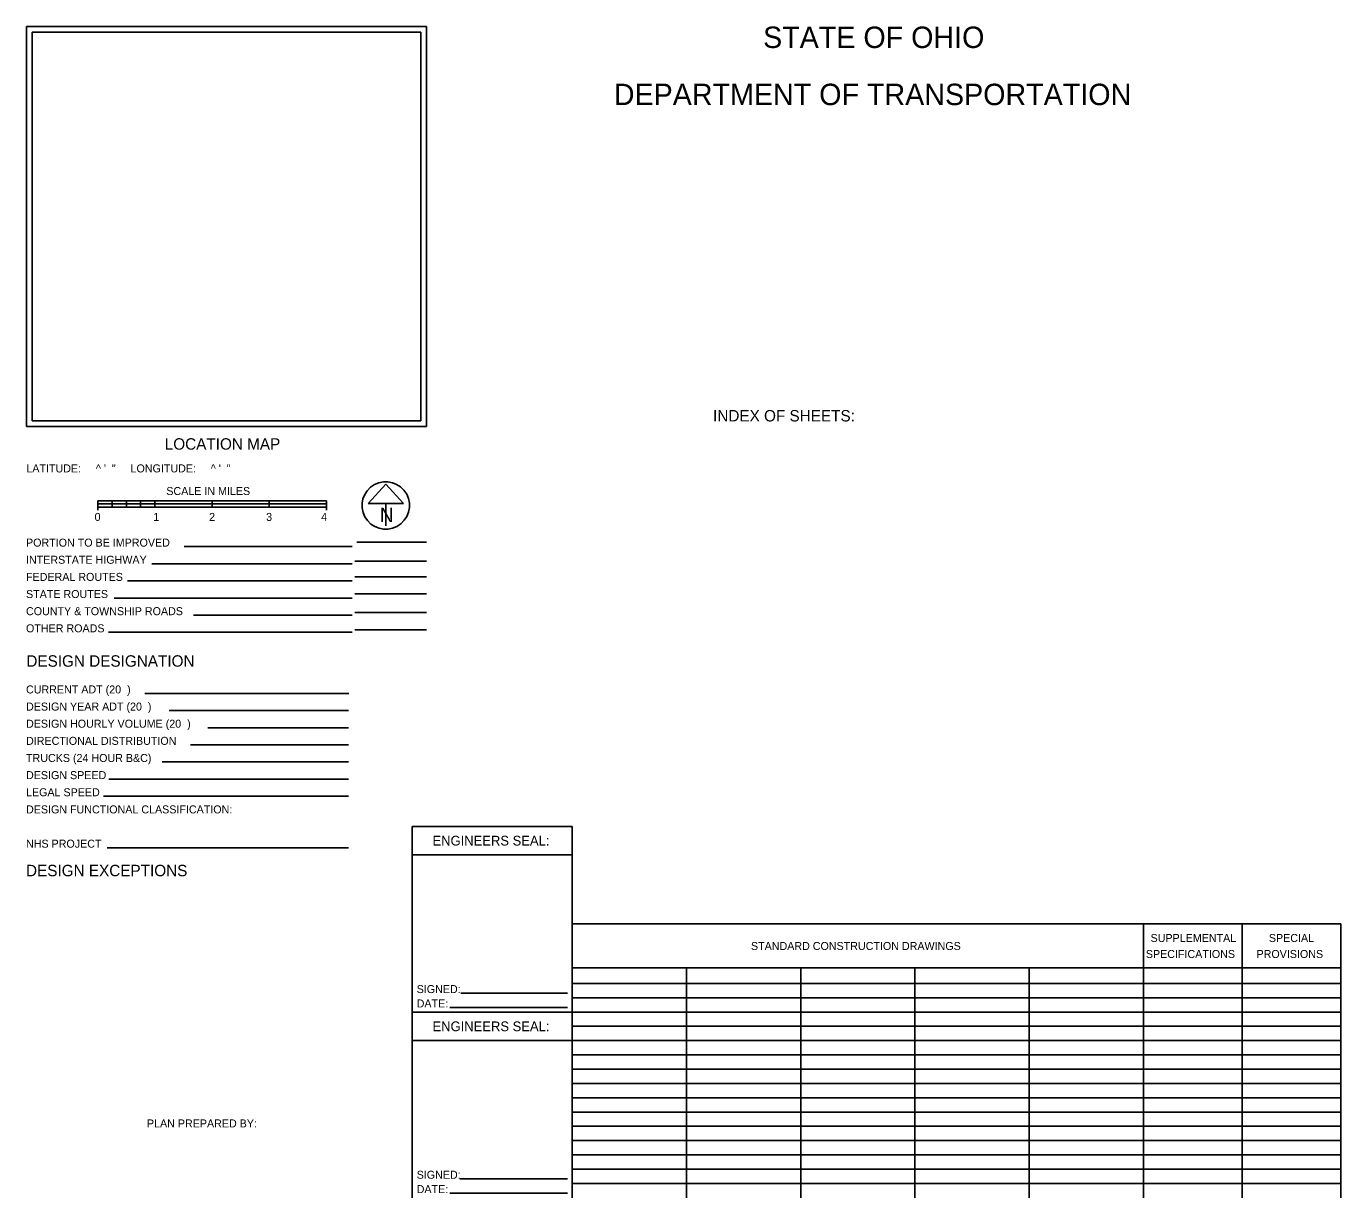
# Model space of a CAD drawing. Extents: x 1862092.2 to 1862141.4, y 420599.8 to 420643.6.
# Drawn here: x 1862099.48 to 1862122.48, y 420623.12 to 420643.62 of the extents above; entities that cross this region are included whole.
import ezdxf

# ---------------------------------------------------------------- set-up
doc = ezdxf.new("R2010")
doc.units = 0
doc.layers.add('SH_Data', color=7, linetype='Continuous')

msp = doc.modelspace()

# ---------------------------------------------------------------- linework, layer by layer
at = {"layer": 'SH_Data'}
for p, q in [((1862099.479, 420643.616), (1862106.479, 420643.616)), ((1862099.479, 420643.616), (1862099.479, 420636.616)), ((1862099.579, 420643.516), (1862099.579, 420636.716)), ((1862099.579, 420643.516), (1862106.379, 420643.516)), ((1862106.379, 420643.516), (1862106.379, 420636.716)), ((1862106.479, 420643.616), (1862106.479, 420636.616)), ((1862099.479, 420636.616), (1862106.479, 420636.616)), ((1862099.579, 420636.716), (1862106.379, 420636.716)), ((1862105.768, 420635.607), (1862105.461, 420635.265)), ((1862106.076, 420635.265), (1862105.768, 420635.607)), ((1862100.729, 420635.316), (1862100.729, 420635.153)), ((1862100.729, 420635.316), (1862104.729, 420635.316)), ((1862100.729, 420635.316), (1862100.729, 420635.26)), ((1862100.979, 420635.316), (1862100.729, 420635.316)), ((1862100.729, 420635.26), (1862100.979, 420635.26)), ((1862100.729, 420635.26), (1862100.979, 420635.26)), ((1862100.729, 420635.203), (1862104.729, 420635.203)), ((1862100.979, 420635.203), (1862100.979, 420635.316)), ((1862100.979, 420635.26), (1862100.979, 420635.316)), ((1862100.979, 420635.26), (1862101.229, 420635.26)), ((1862101.229, 420635.26), (1862100.979, 420635.26)), ((1862100.979, 420635.26), (1862100.979, 420635.203)), ((1862100.979, 420635.203), (1862101.229, 420635.203)), ((1862101.229, 420635.203), (1862101.229, 420635.316)), ((1862101.229, 420635.316), (1862101.229, 420635.26)), ((1862101.479, 420635.316), (1862101.229, 420635.316)), ((1862101.479, 420635.26), (1862101.229, 420635.26)), ((1862101.229, 420635.203), (1862101.229, 420635.26)), ((1862101.229, 420635.26), (1862101.479, 420635.26)), ((1862101.479, 420635.316), (1862101.479, 420635.203)), ((1862101.479, 420635.26), (1862101.479, 420635.316)), ((1862101.729, 420635.26), (1862101.479, 420635.26)), ((1862101.729, 420635.26), (1862101.479, 420635.26)), ((1862101.479, 420635.26), (1862101.479, 420635.203)), ((1862101.479, 420635.203), (1862101.729, 420635.203)), ((1862101.729, 420635.203), (1862101.729, 420635.316)), ((1862101.729, 420635.316), (1862101.729, 420635.26)), ((1862102.729, 420635.316), (1862101.729, 420635.316)), ((1862102.729, 420635.26), (1862101.729, 420635.26)), ((1862101.729, 420635.203), (1862101.729, 420635.26)), ((1862101.729, 420635.26), (1862102.729, 420635.26)), ((1862102.729, 420635.316), (1862102.729, 420635.203)), ((1862102.729, 420635.26), (1862102.729, 420635.316)), ((1862103.729, 420635.26), (1862102.729, 420635.26)), ((1862103.729, 420635.26), (1862102.729, 420635.26)), ((1862102.729, 420635.26), (1862102.729, 420635.203)), ((1862102.729, 420635.203), (1862103.729, 420635.203)), ((1862103.729, 420635.203), (1862103.729, 420635.316)), ((1862104.729, 420635.316), (1862103.729, 420635.316)), ((1862103.729, 420635.316), (1862103.729, 420635.26)), ((1862104.729, 420635.26), (1862103.729, 420635.26)), ((1862103.729, 420635.203), (1862103.729, 420635.26)), ((1862103.729, 420635.26), (1862104.729, 420635.26)), ((1862104.729, 420635.153), (1862104.729, 420635.316)), ((1862104.729, 420635.26), (1862104.729, 420635.316)), ((1862105.461, 420635.265), (1862106.076, 420635.265)), ((1862105.768, 420635.265), (1862105.768, 420634.879)), ((1862105.768, 420635.233), (1862105.768, 420635.233)), ((1862105.768, 420635.233), (1862105.768, 420635.233)), ((1862105.179, 420634.513), (1862102.238, 420634.513)), ((1862105.262, 420634.592), (1862106.479, 420634.592)), ((1862106.479, 420634.257), (1862105.229, 420634.257)), ((1862105.179, 420634.213), (1862101.674, 420634.213)), ((1862105.179, 420633.913), (1862101.248, 420633.913)), ((1862106.479, 420633.986), (1862105.229, 420633.986)), ((1862105.179, 420633.613), (1862101.016, 420633.613)), ((1862106.479, 420633.686), (1862105.229, 420633.686)), ((1862106.479, 420633.359), (1862105.229, 420633.359)), ((1862105.179, 420633.313), (1862102.403, 420633.313)), ((1862105.179, 420633.013), (1862100.914, 420633.013)), ((1862106.479, 420633.059), (1862105.229, 420633.059)), ((1862105.121, 420631.943), (1862101.553, 420631.943)), ((1862105.116, 420631.643), (1862101.978, 420631.643)), ((1862105.116, 420631.343), (1862102.655, 420631.343)), ((1862105.116, 420631.043), (1862102.35, 420631.043)), ((1862105.116, 420630.743), (1862101.854, 420630.743)), ((1862105.116, 420630.443), (1862100.921, 420630.443)), ((1862105.116, 420630.143), (1862100.83, 420630.143)), ((1862106.229, 420626.366), (1862106.229, 420629.616)), ((1862106.229, 420629.616), (1862109.029, 420629.616)), ((1862109.029, 420623.116), (1862109.029, 420629.616)), ((1862105.116, 420629.243), (1862100.891, 420629.243)), ((1862106.229, 420629.116), (1862109.029, 420629.116)), ((1862109.029, 420627.908), (1862122.479, 420627.908)), ((1862119.029, 420623.116), (1862119.029, 420627.908)), ((1862120.754, 420623.116), (1862120.754, 420627.908)), ((1862122.479, 420623.116), (1862122.479, 420627.908)), ((1862109.029, 420627.137), (1862122.479, 420627.137)), ((1862111.029, 420623.116), (1862111.029, 420627.137)), ((1862113.029, 420623.116), (1862113.029, 420627.137)), ((1862115.029, 420623.116), (1862115.029, 420627.137)), ((1862117.029, 420623.116), (1862117.029, 420627.137)), ((1862107.083, 420626.698), (1862108.95, 420626.698)), ((1862109.029, 420626.866), (1862122.479, 420626.866)), ((1862106.887, 420626.446), (1862108.95, 420626.446)), ((1862109.029, 420626.616), (1862122.479, 420626.616)), ((1862106.229, 420623.116), (1862106.229, 420626.366)), ((1862106.229, 420626.366), (1862109.029, 420626.366)), ((1862109.029, 420626.366), (1862122.479, 420626.366)), ((1862109.029, 420626.116), (1862122.479, 420626.116)), ((1862106.229, 420625.866), (1862109.029, 420625.866)), ((1862109.029, 420625.866), (1862122.479, 420625.866)), ((1862109.029, 420625.616), (1862122.479, 420625.616)), ((1862109.029, 420625.366), (1862122.479, 420625.366)), ((1862109.029, 420625.116), (1862122.479, 420625.116)), ((1862109.029, 420624.866), (1862122.479, 420624.866)), ((1862109.029, 420624.616), (1862122.479, 420624.616)), ((1862109.029, 420624.366), (1862122.479, 420624.366)), ((1862109.029, 420624.116), (1862122.479, 420624.116)), ((1862109.029, 420623.866), (1862122.479, 420623.866)), ((1862107.065, 420623.448), (1862108.95, 420623.448)), ((1862109.029, 420623.616), (1862122.479, 420623.616)), ((1862109.029, 420623.366), (1862122.479, 420623.366)), ((1862106.887, 420623.196), (1862108.95, 420623.196))]:
    msp.add_line(p, q, dxfattribs=at)
msp.add_arc((1862105.768, 420635.233), 0.415, 129.7798, 129.7633, dxfattribs=at)

# ---------------------------------------------------------------- texts
for s, height, p in [('STATE OF OHIO', 0.375, (1862112.371, 420643.241)), ('DEPARTMENT OF TRANSPORTATION', 0.375, (1862109.759, 420642.241)), ('INDEX OF SHEETS:', 0.2, (1862111.496, 420636.704)), ('LOCATION MAP', 0.2, (1862101.901, 420636.21)), ('LATITUDE:     ^  \'  "     LONGITUDE:     ^  \'  "', 0.14, (1862099.479, 420635.812)), ('SCALE IN MILES', 0.14, (1862101.928, 420635.416)), ('0', 0.14, (1862100.673, 420634.963)), ('1', 0.14, (1862101.7, 420634.963)), ('2', 0.14, (1862102.677, 420634.963)), ('3', 0.14, (1862103.675, 420634.963)), ('4', 0.14, (1862104.637, 420634.963)), ('PORTION TO BE IMPROVED', 0.14, (1862099.473, 420634.513)), ('INTERSTATE HIGHWAY', 0.14, (1862099.473, 420634.213)), ('FEDERAL ROUTES', 0.14, (1862099.473, 420633.913)), ('STATE ROUTES', 0.14, (1862099.473, 420633.613)), ('COUNTY & TOWNSHIP ROADS', 0.14, (1862099.473, 420633.313)), ('OTHER ROADS', 0.14, (1862099.473, 420633.013)), ('DESIGN DESIGNATION', 0.2, (1862099.479, 420632.411)), ('CURRENT ADT (20  )', 0.14, (1862099.473, 420631.943)), ('DESIGN YEAR ADT (20  )', 0.14, (1862099.473, 420631.643)), ('DESIGN HOURLY VOLUME (20  )', 0.14, (1862099.473, 420631.343)), ('DIRECTIONAL DISTRIBUTION', 0.14, (1862099.473, 420631.043)), ('TRUCKS (24 HOUR B&C)', 0.14, (1862099.473, 420630.743)), ('DESIGN SPEED', 0.14, (1862099.473, 420630.443)), ('LEGAL SPEED', 0.14, (1862099.473, 420630.143)), ('DESIGN FUNCTIONAL CLASSIFICATION:', 0.14, (1862099.473, 420629.843)), ('ENGINEERS SEAL:', 0.17, (1862106.586, 420629.281)), ('NHS PROJECT', 0.14, (1862099.473, 420629.243)), ('DESIGN EXCEPTIONS', 0.2, (1862099.473, 420628.743)), ('STANDARD CONSTRUCTION DRAWINGS', 0.14, (1862112.159, 420627.452)), ('SUPPLEMENTAL', 0.14, (1862119.152, 420627.592)), ('SPECIAL', 0.14, (1862121.222, 420627.592)), ('SPECIFICATIONS', 0.14, (1862119.069, 420627.312)), ('PROVISIONS', 0.14, (1862121.006, 420627.312)), ('SIGNED:', 0.14, (1862106.309, 420626.698)), ('DATE:', 0.14, (1862106.309, 420626.446)), ('ENGINEERS SEAL:', 0.17, (1862106.586, 420626.031)), ('PLAN PREPARED BY:', 0.14, (1862101.589, 420624.346)), ('SIGNED:', 0.14, (1862106.309, 420623.448)), ('DATE:', 0.14, (1862106.309, 420623.196))]:
    msp.add_text(s, height=height, dxfattribs=at).set_placement(p)
msp.add_text('N', height=0.25, rotation=360, dxfattribs=at).set_placement((1862105.664, 420634.942))

doc.saveas('drawing.dxf')
